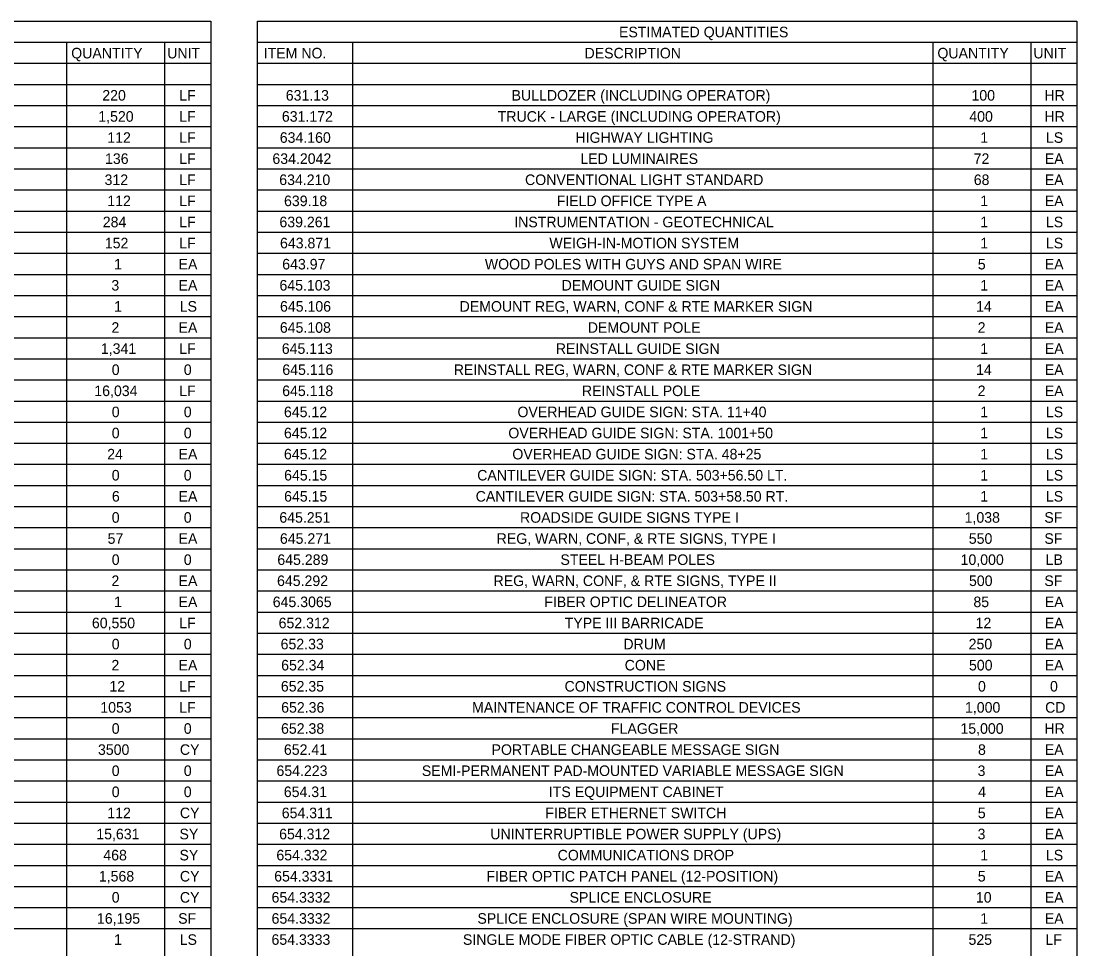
# Model space of a CAD drawing. Extents: x -18.7 to 5.6, y -2.7 to 4.
# Drawn here: x 4.632 to 5.617, y 0.886 to 1.751 of the extents above; entities that cross this region are included whole.
import ezdxf

# ---------------------------------------------------------------- set-up
doc = ezdxf.new("R2010")
doc.units = 0
doc.layers.add('ANNOTATION', color=7, linetype='Continuous')
doc.layers.add('BORDER', color=7, linetype='Continuous')

msp = doc.modelspace()

# ---------------------------------------------------------------- linework, layer by layer
at = {"layer": 'BORDER'}
for p, q in [((3.9448, 1.73155), (4.8091, 1.73155)), ((4.67472, 1.73155), (4.67472, 0.01886)), ((4.76611, 1.73155), (4.76611, 0.01886)), ((4.85265, 1.73155), (5.61696, 1.73155)), ((4.94124, 1.73155), (4.94124, 0.01886)), ((5.48258, 1.73155), (5.48258, 0.01886)), ((5.57397, 1.73155), (5.57397, 0.01886)), ((3.9448, 1.71186), (4.8091, 1.71186)), ((4.85265, 1.71186), (5.61696, 1.71186)), ((3.9448, 1.69217), (4.8091, 1.69217)), ((4.85265, 1.69217), (5.61696, 1.69217)), ((3.9448, 1.67249), (4.8091, 1.67249)), ((4.85265, 1.67249), (5.61696, 1.67249)), ((3.9448, 1.6528), (4.8091, 1.6528)), ((4.85265, 1.6528), (5.61696, 1.6528)), ((3.9448, 1.63312), (4.8091, 1.63312)), ((4.85265, 1.63312), (5.61696, 1.63312)), ((3.9448, 1.61343), (4.8091, 1.61343)), ((4.85265, 1.61343), (5.61696, 1.61343)), ((3.9448, 1.59374), (4.8091, 1.59374)), ((4.85265, 1.59374), (5.61696, 1.59374)), ((3.9448, 1.57406), (4.8091, 1.57406)), ((4.85265, 1.57406), (5.61696, 1.57406)), ((3.9448, 1.55437), (4.8091, 1.55437)), ((4.85265, 1.55437), (5.61696, 1.55437)), ((3.9448, 1.53469), (4.8091, 1.53469)), ((4.85265, 1.53469), (5.61696, 1.53469)), ((3.9448, 1.515), (4.8091, 1.515)), ((4.85265, 1.515), (5.61696, 1.515)), ((3.9448, 1.49531), (4.8091, 1.49531)), ((4.85265, 1.49531), (5.61696, 1.49531)), ((3.9448, 1.47563), (4.8091, 1.47563)), ((4.85265, 1.47563), (5.61696, 1.47563)), ((3.9448, 1.45594), (4.8091, 1.45594)), ((4.85265, 1.45594), (5.61696, 1.45594)), ((3.9448, 1.43626), (4.8091, 1.43626)), ((4.85265, 1.43626), (5.61696, 1.43626)), ((3.9448, 1.41657), (4.8091, 1.41657)), ((4.85265, 1.41657), (5.61696, 1.41657)), ((3.9448, 1.39688), (4.8091, 1.39688)), ((4.85265, 1.39688), (5.61696, 1.39688)), ((3.9448, 1.3772), (4.8091, 1.3772)), ((4.85265, 1.3772), (5.61696, 1.3772)), ((3.9448, 1.35751), (4.8091, 1.35751)), ((4.85265, 1.35751), (5.61696, 1.35751)), ((3.9448, 1.33783), (4.8091, 1.33783)), ((4.85265, 1.33783), (5.61696, 1.33783)), ((3.9448, 1.31814), (4.8091, 1.31814)), ((4.85265, 1.31814), (5.61696, 1.31814)), ((3.9448, 1.29845), (4.8091, 1.29845)), ((4.85265, 1.29845), (5.61696, 1.29845)), ((3.9448, 1.27877), (4.8091, 1.27877)), ((4.85265, 1.27877), (5.61696, 1.27877)), ((3.9448, 1.25908), (4.8091, 1.25908)), ((4.85265, 1.25908), (5.61696, 1.25908)), ((3.9448, 1.2394), (4.8091, 1.2394)), ((4.85265, 1.2394), (5.61696, 1.2394)), ((3.9448, 1.21971), (4.8091, 1.21971)), ((4.85265, 1.21971), (5.61696, 1.21971)), ((3.9448, 1.20002), (4.8091, 1.20002)), ((4.85265, 1.20002), (5.61696, 1.20002)), ((3.9448, 1.18034), (4.8091, 1.18034)), ((4.85265, 1.18034), (5.61696, 1.18034)), ((3.9448, 1.16065), (4.8091, 1.16065)), ((4.85265, 1.16065), (5.61696, 1.16065)), ((3.9448, 1.14097), (4.8091, 1.14097)), ((4.85265, 1.14097), (5.61696, 1.14097)), ((3.9448, 1.12128), (4.8091, 1.12128)), ((4.85265, 1.12128), (5.61696, 1.12128)), ((3.9448, 1.10159), (4.8091, 1.10159)), ((4.85265, 1.10159), (5.61696, 1.10159)), ((3.9448, 1.08191), (4.8091, 1.08191)), ((4.85265, 1.08191), (5.61696, 1.08191)), ((3.9448, 1.06222), (4.8091, 1.06222)), ((4.85265, 1.06222), (5.61696, 1.06222)), ((3.9448, 1.04254), (4.8091, 1.04254)), ((4.85265, 1.04254), (5.61696, 1.04254)), ((3.9448, 1.02285), (4.8091, 1.02285)), ((4.85265, 1.02285), (5.61696, 1.02285)), ((3.9448, 1.00316), (4.8091, 1.00316)), ((4.85265, 1.00316), (5.61696, 1.00316)), ((3.9448, 0.98348), (4.8091, 0.98348)), ((4.85265, 0.98348), (5.61696, 0.98348)), ((3.9448, 0.96379), (4.8091, 0.96379)), ((4.85265, 0.96379), (5.61696, 0.96379)), ((3.9448, 0.94411), (4.8091, 0.94411)), ((4.85265, 0.94411), (5.61696, 0.94411)), ((3.9448, 0.92442), (4.8091, 0.92442)), ((4.85265, 0.92442), (5.61696, 0.92442)), ((3.9448, 0.90473), (4.8091, 0.90473)), ((4.85265, 0.90473), (5.61696, 0.90473))]:
    msp.add_line(p, q, dxfattribs=at)
for points in [[(3.9448, 1.75123), (4.8091, 1.75123), (4.8091, 0.01886), (3.9448, 0.01886)], [(4.85265, 1.75123), (5.61696, 1.75123), (5.61696, 0.01886), (4.85265, 0.01886)]]:
    msp.add_lwpolyline(points, close=True, dxfattribs=at)

# ---------------------------------------------------------------- texts
at = {"layer": 'ANNOTATION'}
for s, height, p in [('220', 0.009843, (4.70801, 1.67708)), ('LF', 0.009843, (4.77978, 1.67708)), ('631.13', 0.009843, (4.87914, 1.67708)), ('BULLDOZER (INCLUDING OPERATOR)', 0.009843, (5.08976, 1.67708)), ('100', 0.009843, (5.51865, 1.67708)), ('HR', 0.009843, (5.58665, 1.67708)), ('1,520', 0.009843, (4.70429, 1.6574)), ('LF', 0.009843, (4.77978, 1.6574)), ('631.172', 0.009843, (4.8755, 1.6574)), ('TRUCK - LARGE (INCLUDING OPERATOR)', 0.009843, (5.0768, 1.6574)), ('400', 0.009843, (5.51664, 1.6574)), ('HR', 0.009843, (5.58665, 1.6574)), ('112', 0.009843, (4.7127, 1.63771)), ('LF', 0.009843, (4.77978, 1.63771)), ('634.160', 0.009843, (4.87353, 1.63771)), ('HIGHWAY LIGHTING', 0.009843, (5.14929, 1.63771)), ('1', 0.00984, (5.52687, 1.63771)), ('LS', 0.009843, (5.58806, 1.63771)), ('136', 0.009843, (4.71057, 1.61803)), ('LF', 0.009843, (4.77978, 1.61803)), ('634.2042', 0.009843, (4.86667, 1.61803)), ('LED LUMINAIRES', 0.009843, (5.15393, 1.61803)), ('72', 0.009843, (5.5207, 1.61803)), ('EA', 0.009843, (5.58701, 1.61803)), ('312', 0.009843, (4.71014, 1.59834)), ('LF', 0.009843, (4.77978, 1.59834)), ('634.210', 0.009843, (4.87306, 1.59834)), ('CONVENTIONAL LIGHT STANDARD', 0.009843, (5.10228, 1.59834)), ('68', 0.009843, (5.52078, 1.59834)), ('EA', 0.009843, (5.58701, 1.59834)), ('112', 0.009843, (4.7127, 1.57865)), ('LF', 0.009843, (4.77978, 1.57865)), ('639.18', 0.009843, (4.87752, 1.57865)), ('FIELD OFFICE TYPE A', 0.009843, (5.13182, 1.57865)), ('1', 0.00984, (5.52687, 1.57865)), ('EA', 0.009843, (5.58701, 1.57865)), ('284', 0.009843, (4.70847, 1.55897)), ('LF', 0.009843, (4.77978, 1.55897)), ('639.261', 0.009843, (4.87322, 1.55897)), ('INSTRUMENTATION - GEOTECHNICAL', 0.009843, (5.0922, 1.55897)), ('1', 0.00984, (5.52687, 1.55897)), ('LS', 0.009843, (5.58806, 1.55897)), ('152', 0.009843, (4.71037, 1.53928)), ('LF', 0.009843, (4.77978, 1.53928)), ('643.871', 0.009843, (4.87376, 1.53928)), ('WEIGH-IN-MOTION SYSTEM', 0.009843, (5.12498, 1.53928)), ('1', 0.00984, (5.52687, 1.53928)), ('LS', 0.009843, (5.58806, 1.53928)), ('1', 0.00984, (4.71901, 1.5196)), ('EA', 0.009843, (4.77916, 1.5196)), ('643.97', 0.009843, (4.87585, 1.5196)), ('WOOD POLES WITH GUYS AND SPAN WIRE', 0.009843, (5.06478, 1.5196)), ('5', 0.00984, (5.52458, 1.5196)), ('EA', 0.009843, (5.58701, 1.5196)), ('3', 0.00984, (4.71649, 1.49991)), ('EA', 0.009843, (4.77916, 1.49991)), ('645.103', 0.009843, (4.87325, 1.49991)), ('DEMOUNT GUIDE SIGN', 0.009843, (5.13644, 1.49991)), ('1', 0.00984, (5.52687, 1.49991)), ('EA', 0.009843, (5.58701, 1.49991)), ('1', 0.00984, (4.71901, 1.48022)), ('LS', 0.009843, (4.78021, 1.48022)), ('645.106', 0.009843, (4.87376, 1.48022)), ('DEMOUNT REG, WARN, CONF & RTE MARKER SIGN', 0.009843, (5.04127, 1.48022)), ('14', 0.009843, (5.52292, 1.48022)), ('EA', 0.009843, (5.58701, 1.48022)), ('2', 0.00984, (4.71657, 1.46054)), ('EA', 0.009843, (4.77916, 1.46054)), ('645.108', 0.009843, (4.87364, 1.46054)), ('DEMOUNT POLE', 0.009843, (5.1608, 1.46054)), ('2', 0.00984, (5.52442, 1.46054)), ('EA', 0.009843, (5.58701, 1.46054)), ('1,341', 0.009843, (4.7067, 1.44085)), ('LF', 0.009843, (4.77978, 1.44085)), ('645.113', 0.009843, (4.87542, 1.44085)), ('REINSTALL GUIDE SIGN', 0.009843, (5.13098, 1.44085)), ('1', 0.00984, (5.52687, 1.44085)), ('EA', 0.009843, (5.58701, 1.44085)), ('0', 0.00984, (4.71684, 1.42117)), ('0', 0.00984, (4.78404, 1.42117)), ('645.116', 0.009843, (4.87593, 1.42117)), ('REINSTALL REG, WARN, CONF & RTE MARKER SIGN', 0.009843, (5.03581, 1.42117)), ('14', 0.009843, (5.52292, 1.42117)), ('EA', 0.009843, (5.58701, 1.42117)), ('16,034', 0.009843, (4.70058, 1.40148)), ('LF', 0.009843, (4.77978, 1.40148)), ('645.118', 0.009843, (4.87581, 1.40148)), ('REINSTALL POLE', 0.009843, (5.15534, 1.40148)), ('2', 0.00984, (5.52442, 1.40148)), ('EA', 0.009843, (5.58701, 1.40148)), ('0', 0.00984, (4.71684, 1.38179)), ('0', 0.00984, (4.78404, 1.38179)), ('645.12', 0.009843, (4.87744, 1.38179)), ('OVERHEAD GUIDE SIGN: STA. 11+40', 0.009843, (5.09522, 1.38179)), ('1', 0.00984, (5.52687, 1.38179)), ('LS', 0.009843, (5.58806, 1.38179)), ('0', 0.00984, (4.71684, 1.36211)), ('0', 0.00984, (4.78404, 1.36211)), ('645.12', 0.009843, (4.87744, 1.36211)), ('OVERHEAD GUIDE SIGN: STA. 1001+50', 0.009843, (5.08669, 1.36211)), ('1', 0.00984, (5.52687, 1.36211)), ('LS', 0.009843, (5.58806, 1.36211)), ('24', 0.009843, (4.71258, 1.34242)), ('EA', 0.009843, (4.77916, 1.34242)), ('645.12', 0.009843, (4.87744, 1.34242)), ('OVERHEAD GUIDE SIGN: STA. 48+25', 0.009843, (5.09045, 1.34242)), ('1', 0.00984, (5.52687, 1.34242)), ('LS', 0.009843, (5.58806, 1.34242)), ('0', 0.00984, (4.71684, 1.32274)), ('0', 0.00984, (4.78404, 1.32274)), ('645.15', 0.009843, (4.87759, 1.32274)), ('CANTILEVER GUIDE SIGN: STA. 503+56.50 LT.', 0.009843, (5.05766, 1.32274)), ('1', 0.00984, (5.52687, 1.32274)), ('LS', 0.009843, (5.58806, 1.32274)), ('6', 0.00984, (4.71699, 1.30305)), ('EA', 0.009843, (4.77916, 1.30305)), ('645.15', 0.009843, (4.87759, 1.30305)), ('CANTILEVER GUIDE SIGN: STA. 503+58.50 RT.', 0.009843, (5.05626, 1.30305)), ('1', 0.00984, (5.52687, 1.30305)), ('LS', 0.009843, (5.58806, 1.30305)), ('0', 0.00984, (4.71684, 1.28336)), ('0', 0.00984, (4.78404, 1.28336)), ('645.251', 0.009843, (4.87314, 1.28336)), ('ROADSIDE GUIDE SIGNS TYPE I ', 0.009843, (5.0976, 1.28336)), ('1,038', 0.009843, (5.51227, 1.28336)), ('SF', 0.009843, (5.58663, 1.28336)), ('57', 0.009843, (4.71297, 1.26368)), ('EA', 0.009843, (4.77916, 1.26368)), ('645.271', 0.009843, (4.87368, 1.26368)), ('REG, WARN, CONF, & RTE SIGNS, TYPE I', 0.009843, (5.07581, 1.26368)), ('550', 0.009843, (5.51617, 1.26368)), ('SF', 0.009843, (5.58663, 1.26368)), ('0', 0.00984, (4.71684, 1.24399)), ('0', 0.00984, (4.78404, 1.24399)), ('645.289', 0.009843, (4.87128, 1.24399)), ('STEEL H-BEAM POLES', 0.009843, (5.1353, 1.24399)), ('10,000', 0.009843, (5.50851, 1.24399)), ('LB', 0.009843, (5.58783, 1.24399)), ('2', 0.00984, (4.71657, 1.22431)), ('EA', 0.009843, (4.77916, 1.22431)), ('645.292', 0.009843, (4.87101, 1.22431)), ('REG, WARN, CONF, & RTE SIGNS, TYPE II', 0.009843, (5.07289, 1.22431)), ('500', 0.009843, (5.51633, 1.22431)), ('SF', 0.009843, (5.58663, 1.22431)), ('1', 0.00984, (4.71901, 1.20462)), ('EA', 0.009843, (4.77916, 1.20462)), ('645.3065', 0.009843, (4.86698, 1.20462)), ('FIBER OPTIC DELINEATOR', 0.009843, (5.12024, 1.20462)), ('85', 0.009843, (5.52047, 1.20462)), ('EA', 0.009843, (5.58701, 1.20462)), ('60,550', 0.009843, (4.69833, 1.18493)), ('LF', 0.009843, (4.77978, 1.18493)), ('652.312', 0.009843, (4.87248, 1.18493)), ('TYPE III BARRICADE', 0.009843, (5.13927, 1.18493)), ('12', 0.009843, (5.52249, 1.18493)), ('EA', 0.009843, (5.58701, 1.18493)), ('0', 0.00984, (4.71684, 1.16525)), ('0', 0.00984, (4.78404, 1.16525)), ('652.33', 0.009843, (4.87434, 1.16525)), ('DRUM', 0.009843, (5.19401, 1.16525)), ('250', 0.009843, (5.51602, 1.16525)), ('EA', 0.009843, (5.58701, 1.16525)), ('2', 0.00984, (4.71657, 1.14556)), ('EA', 0.009843, (4.77916, 1.14556)), ('652.34', 0.009843, (4.87484, 1.14556)), ('CONE', 0.009843, (5.19524, 1.14556)), ('500', 0.009843, (5.51633, 1.14556)), ('EA', 0.009843, (5.58701, 1.14556)), ('12', 0.009843, (4.71463, 1.12588)), ('LF', 0.009843, (4.77978, 1.12588)), ('652.35', 0.009843, (4.87457, 1.12588)), ('CONSTRUCTION SIGNS', 0.009843, (5.13917, 1.12588)), ('0', 0.00984, (5.5247, 1.12588)), ('0', 0.00984, (5.5919, 1.12588)), ('1053', 0.009843, (4.70619, 1.10619)), ('LF', 0.009843, (4.77978, 1.10619)), ('652.36', 0.009843, (4.87484, 1.10619)), ('MAINTENANCE OF TRAFFIC CONTROL DEVICES', 0.009843, (5.05289, 1.10619)), ('1,000', 0.009843, (5.51262, 1.10619)), ('CD', 0.009843, (5.58733, 1.10619)), ('0', 0.00984, (4.71684, 1.0865)), ('0', 0.00984, (4.78404, 1.0865)), ('652.38', 0.009843, (4.87472, 1.0865)), ('FLAGGER', 0.009843, (5.18237, 1.0865)), ('15,000', 0.009843, (5.50835, 1.0865)), ('HR', 0.009843, (5.58665, 1.0865)), ('3500', 0.009843, (4.70398, 1.06682)), ('CY', 0.009843, (4.7804, 1.06682)), ('652.41', 0.009843, (4.8774, 1.06682)), ('PORTABLE CHANGEABLE MESSAGE SIGN', 0.009843, (5.07106, 1.06682)), ('8', 0.00984, (5.52474, 1.06682)), ('EA', 0.009843, (5.58701, 1.06682)), ('0', 0.00984, (4.71684, 1.04713)), ('0', 0.00984, (4.78404, 1.04713)), ('654.223', 0.009843, (4.87046, 1.04713)), ('SEMI-PERMANENT PAD-MOUNTED VARIABLE MESSAGE SIGN', 0.009843, (5.00605, 1.04713)), ('3', 0.00984, (5.52435, 1.04713)), ('EA', 0.009843, (5.58701, 1.04713)), ('0', 0.00984, (4.71684, 1.02745)), ('0', 0.00984, (4.78404, 1.02745)), ('654.31', 0.009843, (4.87732, 1.02745)), ('ITS EQUIPMENT CABINET', 0.009843, (5.12449, 1.02745)), ('4', 0.00984, (5.52485, 1.02745)), ('EA', 0.009843, (5.58701, 1.02745)), ('112', 0.009843, (4.7127, 1.00776)), ('CY', 0.009843, (4.7804, 1.00776)), ('654.311', 0.009843, (4.87539, 1.00776)), ('FIBER ETHERNET SWITCH', 0.009843, (5.12116, 1.00776)), ('5', 0.00984, (5.52458, 1.00776)), ('EA', 0.009843, (5.58701, 1.00776)), ('15,631', 0.009843, (4.70244, 0.98807)), ('SY', 0.009843, (4.78001, 0.98807)), ('654.312', 0.009843, (4.87294, 0.98807)), ('UNINTERRUPTIBLE POWER SUPPLY (UPS)', 0.009843, (5.0699, 0.98807)), ('3', 0.00984, (5.52435, 0.98807)), ('EA', 0.009843, (5.58701, 0.98807)), ('468', 0.009843, (4.70898, 0.96839)), ('SY', 0.009843, (4.78001, 0.96839)), ('654.332', 0.009843, (4.87039, 0.96839)), ('COMMUNICATIONS DROP', 0.009843, (5.13272, 0.96839)), ('1', 0.00984, (5.52687, 0.96839)), ('LS', 0.009843, (5.58806, 0.96839)), ('1,568', 0.009843, (4.7048, 0.9487)), ('CY', 0.009843, (4.7804, 0.9487)), ('654.3331', 0.009843, (4.86834, 0.9487)), ('FIBER OPTIC PATCH PANEL (12-POSITION)', 0.009843, (5.06628, 0.9487)), ('5', 0.00984, (5.52458, 0.9487)), ('EA', 0.009843, (5.58701, 0.9487)), ('0', 0.00984, (4.71684, 0.92902)), ('CY', 0.009843, (4.7804, 0.92902)), ('654.3332', 0.009843, (4.86589, 0.92902)), ('SPLICE ENCLOSURE', 0.009843, (5.14382, 0.92902)), ('10', 0.009843, (5.52276, 0.92902)), ('EA', 0.009843, (5.58701, 0.92902)), ('16,195', 0.009843, (4.70302, 0.90933)), ('SF', 0.009843, (4.77877, 0.90933)), ('654.3332', 0.009843, (4.86589, 0.90933)), ('SPLICE ENCLOSURE (SPAN WIRE MOUNTING)', 0.009843, (5.05787, 0.90933)), ('1', 0.00984, (5.52687, 0.90933)), ('EA', 0.009843, (5.58701, 0.90933)), ('1', 0.00984, (4.71901, 0.88964)), ('LS', 0.009843, (4.78021, 0.88964)), ('654.3333', 0.009843, (4.86582, 0.88964)), ('SINGLE MODE FIBER OPTIC CABLE (12-STRAND)', 0.009843, (5.04436, 0.88964)), ('525', 0.009843, (5.5159, 0.88964)), ('LF', 0.009843, (5.58764, 0.88964))]:
    msp.add_text(s, height=height, dxfattribs=at).set_placement(p)
at = {"layer": 'BORDER'}
for s, height, p in [('ESTIMATED QUANTITIES', 0.0098425, (5.18993, 1.73614)), ('QUANTITY', 0.009843, (4.67903, 1.71646)), ('UNIT', 0.009843, (4.76854, 1.71646)), ('ITEM NO.', 0.009843, (4.85856, 1.71646)), ('DESCRIPTION', 0.0098425, (5.15777, 1.71646)), ('QUANTITY', 0.009843, (5.48689, 1.71646)), ('UNIT', 0.009843, (5.5764, 1.71646))]:
    msp.add_text(s, height=height, dxfattribs=at).set_placement(p)

doc.saveas('drawing.dxf')
